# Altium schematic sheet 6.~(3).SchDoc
size 420 x 297 mm
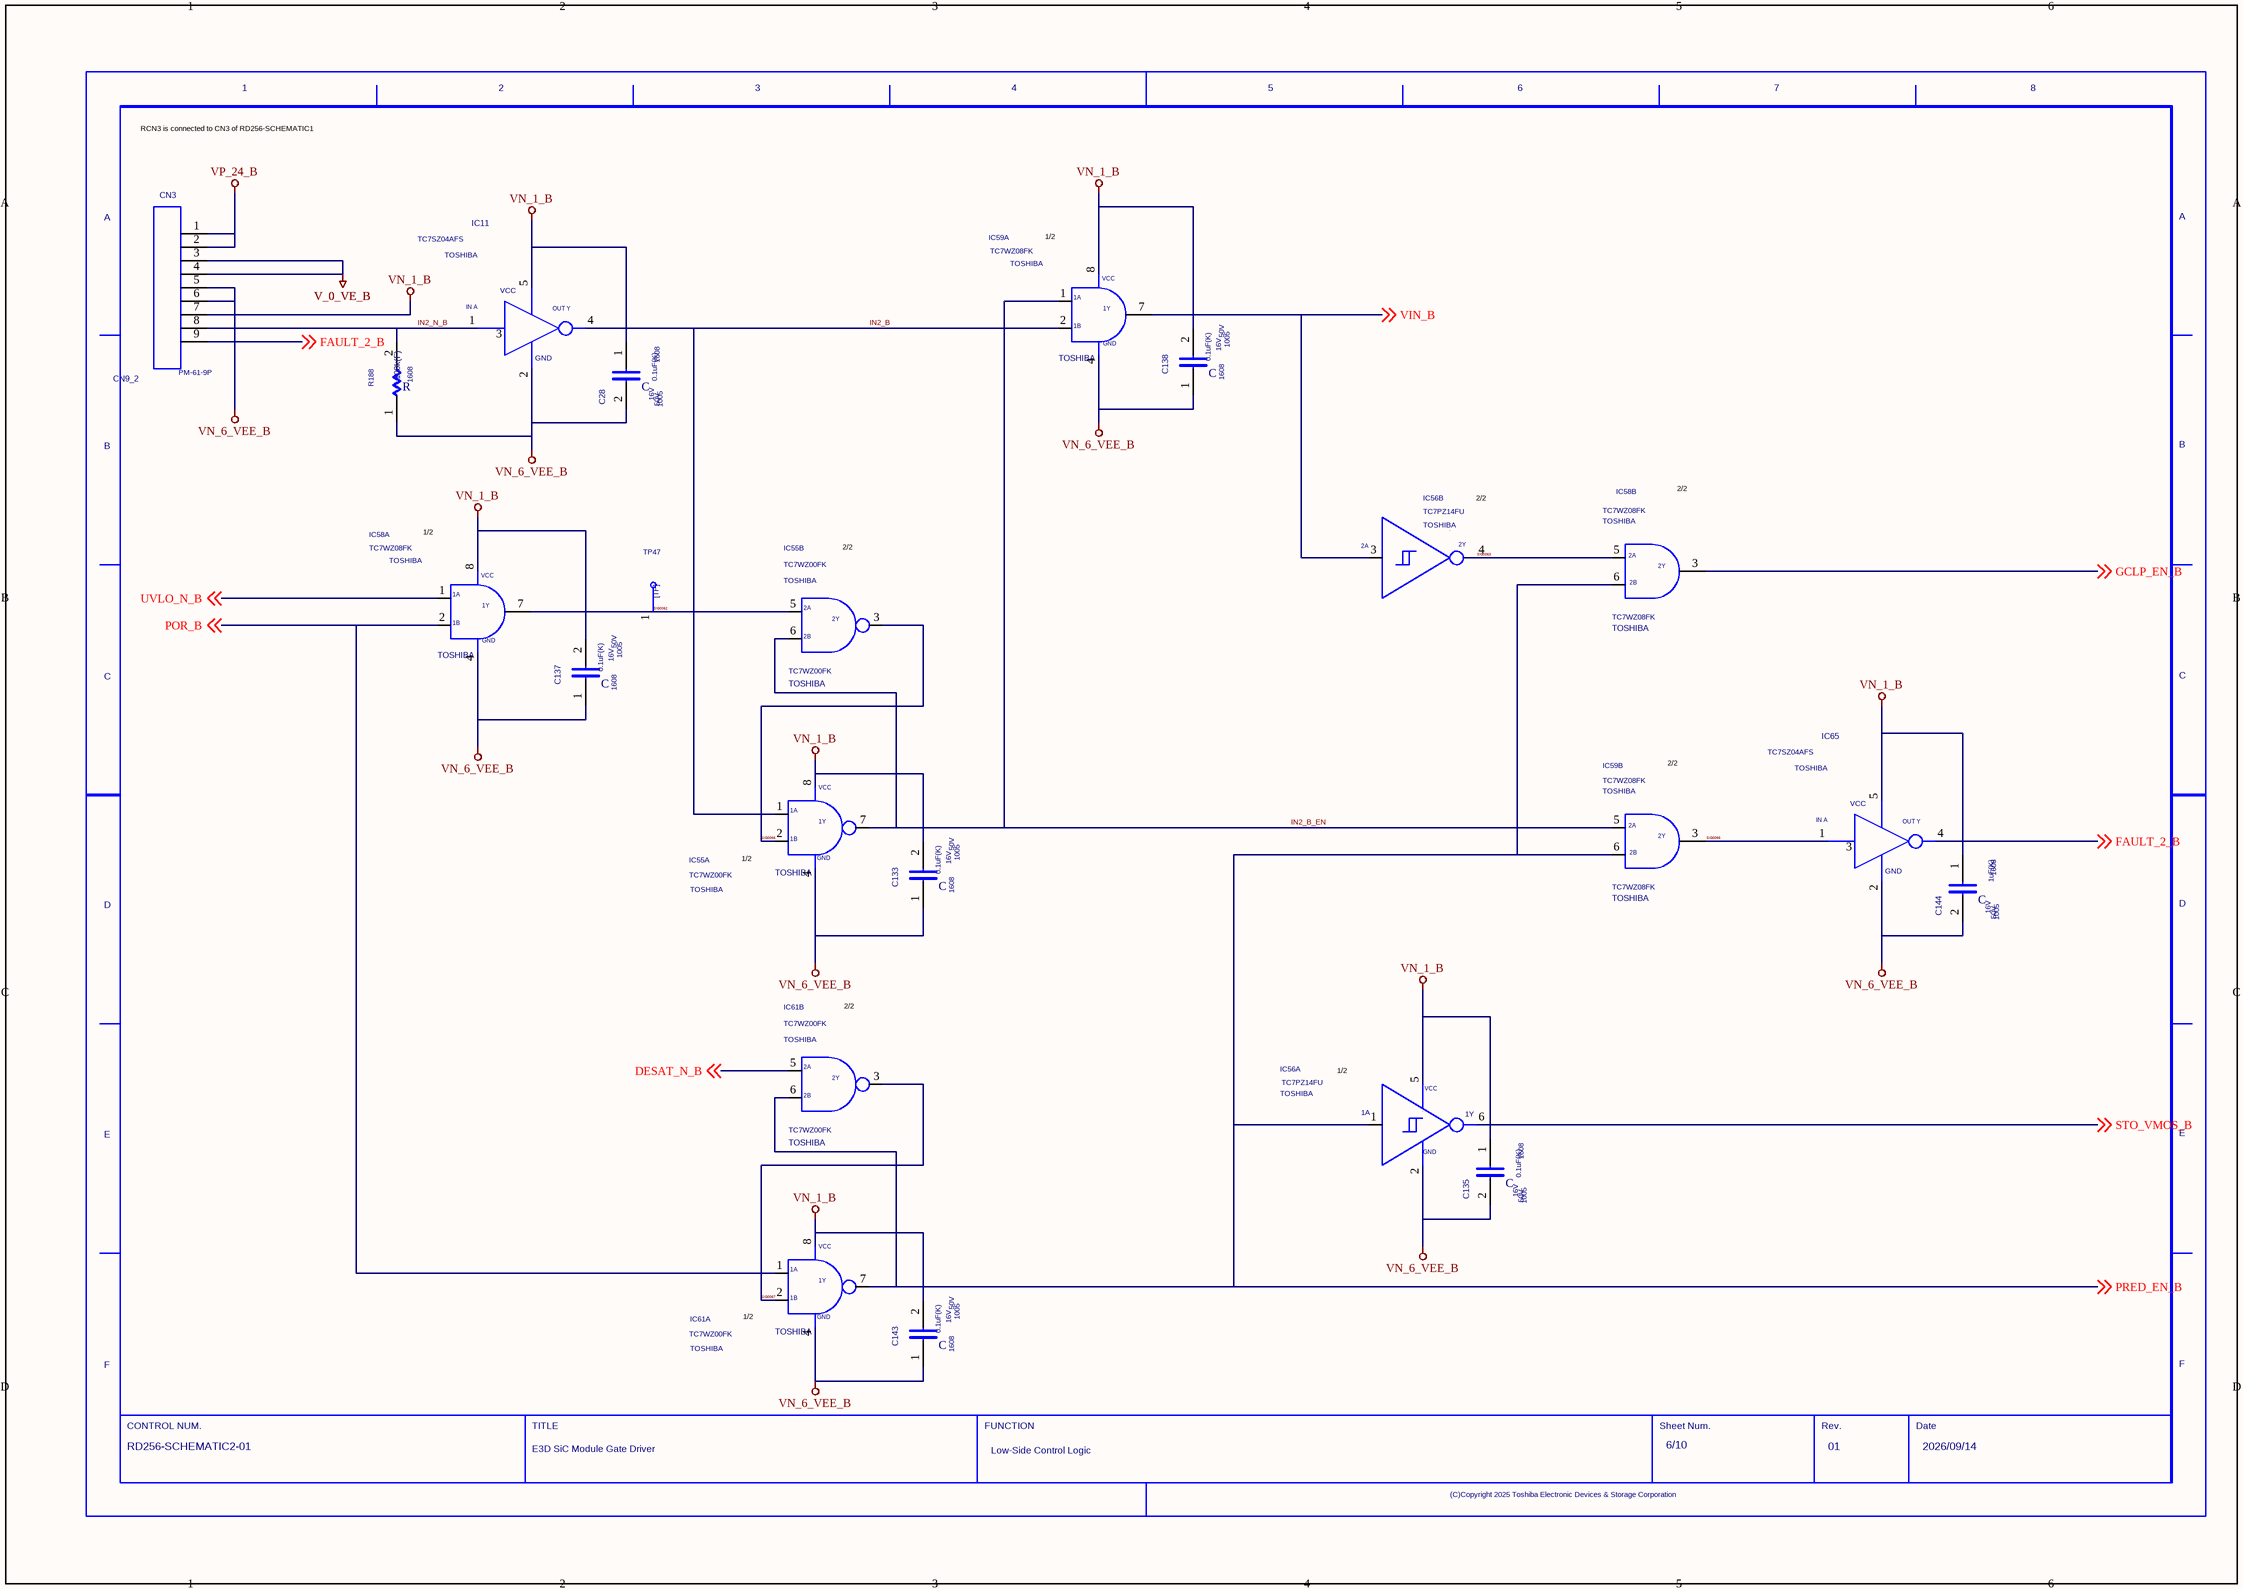
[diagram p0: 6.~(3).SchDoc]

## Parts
C28  VOLTAGE: 16V  CODE: 1005  VAL1: 0.1uF(K)  VAL2: 50V  SIZECODESMD: 1608  (hidden comment: C)
C133  VOLTAGE: 16V  CODE: 1005  VAL1: 0.1uF(K)  VAL2: 50V  SIZECODESMD: 1608  (hidden comment: C)
C135  VOLTAGE: 16V  CODE: 1005  VAL1: 0.1uF(K)  VAL2: 50V  SIZECODESMD: 1608  (hidden comment: C)
C137  VOLTAGE: 16V  CODE: 1005  VAL1: 0.1uF(K)  VAL2: 50V  SIZECODESMD: 1608  (hidden comment: C)
C138  VOLTAGE: 16V  CODE: 1005  VAL1: 0.1uF(K)  VAL2: 50V  SIZECODESMD: 1608  (hidden comment: C)
C143  VOLTAGE: 16V  CODE: 1005  VAL1: 0.1uF(K)  VAL2: 50V  SIZECODESMD: 1608  (hidden comment: C)
C144  VOLTAGE: 16V  CODE: 1005  VAL1: 1uF(K)  VAL2: 50V  SIZECODESMD: 1608  (hidden comment: C)
CN3  CN9_2  VAL3: PM-61-9P
IC11  USERCOMPTEXT3: TOSHIBA  (hidden comment: TC7SZ04AFS)
IC55  VENDOR: TOSHIBA  (hidden comment: TC7WZ00FK)  (parts A,B of 2)
IC56  VAL3: TC7PZ14FU  USERCOMPTEXT3: TOSHIBA  (hidden comment: TC7PZ17FU)  (parts A,B of 2)
IC58  VENDOR: TOSHIBA  (hidden comment: TC7WZ08FK)  (parts A,B of 2)
IC59  VENDOR: TOSHIBA  (hidden comment: TC7WZ08FK)  (parts A,B of 2)
IC61  VENDOR: TOSHIBA  (hidden comment: TC7WZ00FK)  (parts A,B of 2)
IC65  USERCOMPTEXT3: TOSHIBA  (hidden comment: TC7SZ04AFS)
R188  VAL1: 100k(F)  SIZECODESMD: 1608  (hidden comment: R)
TP47  TP  (value not drawn)
U?  REVISION: 01  SHEETNUMBER: 6/10  FUNCTION: Low-Side Control Logic  TITLE: E3D SiC Module Gate Driver  DRAWINGNUMBER: RD256-SCHEMATIC2-01  DATE: 2026/09/14  (hidden comment: WAKU_DEF100)

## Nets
V_0_VE_B: CN3.3 CN3.4
VN_1_B: C28.1 C133.2 C135.1 C137.2 C138.2 C143.2 C144.1 CN3.7 IC11.5 IC55.8 IC56.5 IC58.8 IC59.8 IC61.8 IC65.5
VN_6_VEE_B: C28.2 C133.1 C135.2 C137.1 C138.1 C143.1 C144.2 CN3.5 CN3.6 IC11.2 IC55.4 IC56.2 IC58.4 IC59.4 IC61.4 IC65.2 R188.1
VP_24_B: CN3.1 CN3.2
DESAT_N_B: IC61.5(2A) ; off-sheet DESAT_N_B
FAULT_2_B: CN3.9 IC65.4 ; off-sheet FAULT_2_B
GCLP_EN_B: IC58.3 ; off-sheet GCLP_EN_B
IN2_B: IC11.4 IC55.1 IC59.2
IN2_B_EN: IC55.6(2B) IC55.7 IC59.1 IC59.5
IN2_N_B: CN3.8 IC11.1 R188.2
POR_B: IC58.2 IC61.1 ; off-sheet POR_B
PRED_EN_B: IC56.1 IC58.6 IC59.6 IC61.6(2B) IC61.7 ; off-sheet PRED_EN_B
SIG0062: IC55.5(2A) IC58.7 TP47.1
SIG0063: IC56.4 IC58.5
SIG0065: IC59.3 IC65.1
SIG0066: IC55.2 IC55.3(2Y)
SIG0067: IC61.2 IC61.3(2Y)
STO_VMOS_B: IC56.6 ; off-sheet STO_VMOS_B
UVLO_N_B: IC58.1 ; off-sheet UVLO_N_B
VIN_B: IC56.3 IC59.7 ; off-sheet VIN_B

Not connected (* = marked no-connect by the designer): IC11 3; IC65 3

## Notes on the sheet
- RCN3 is connected to CN3 of RD256-SCHEMATIC1
- (near IC59) 1/2
- (near IC58) 1/2
- 2/2
- (near IC55) 1/2
- (near IC56) 1/2
- (near IC61) 1/2

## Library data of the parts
C28 C133 C135 C137 C138 C143 C144 = C: ORIGINALSYMBOLORIGIN: (0,0); VC2: 0; PSPICETEMPLATE: C^@REFDES %1 %2 ?TOLERANCE¦C^@REFDES¦ @VALUE ?IC/IC=@IC/ TC=@TC1,@TC2 ?TOLERANCE¦\n.model C^@REFDES CAP C=1 DEV=@TOLERANCE% TC1=@TC1 TC2=@TC2 VC1=@VC1 VC2=@VC2¦; SAVECOUNT: 2; UPDATETIME: 08:48:12; UPDATEUSER: HP_Z8_KEYSHOT; INSTANCENAME: INS2265204
CN3 = CN9_1: OriginalSymbolOrigin: (0,0); USER_VALUE: XG4A-1031; PSPICETEMPLATE: X^@REFDES %1 %2 %3 %4 %5 %6 %7 %8 %9 %10 %M1 %M2 @MODEL; SAVECOUNT: 2; UPDATETIME: 08:48:13; UPDATEUSER: HP_Z8_KEYSHOT; INSTANCENAME: INS2253568
IC11 IC65 = TC7SZ04AFS: OriginalSymbolOrigin: (0,-5080); PSPICETEMPLATE: X^@REFDES %INA %GND %NC %OUTY %VCC @MODEL; SAVECOUNT: 6; UPDATETIME: 19:30:29; UPDATEUSER: t5459927; TIME: 11:55:02; INSTANCENAME: INS2254048
IC55 IC61 = TC7WZ00FK_2: PART NUMBER: TC7W00FK; ORIGINALSYMBOLORIGIN: (2540,-2540); DESCRIPTION-A: NAND 2ch Logic; PSPICETEMPLATE: X^@REFDES %1A %1B %2Y %GND %2A %2B %1Y %VCC @MODEL; ・: 7 V; SPLIT_INST: TRUE; ORDER: $pOrder; SWAP_INFO: (S1+S2); SAVECOUNT: 5; UPDATETIME: 16:09:46; UPDATEUSER: sptcae09; TIME: 08:52:39; INSTANCENAME: INS2253652; FUNCN: TC7WZ00FK_1; CaptureCellPackProp: TC7WZ00FK_2A
IC56 = TC7PZ14FU_2: OriginalSymbolOrigin: (5080,15240); SWAP_INFO: (S1+S2); PSPICETEMPLATE: X^@REFDES %1A %GND %2A %2Y %VCC %1Y @MODEL; SPLIT_INST: TRUE; SAVECOUNT: 7; UPDATETIME: 19:09:34; UPDATEUSER: t5459927; TIME: 11:55:01; INSTANCENAME: INS2254016; FUNCN: TC7PZ14FU_1; CaptureCellPackProp: TC7PZ14FU_2A
IC58 IC59 = TC7WZ08FK_1: PART NUMBER: TC7W00FK; ORIGINALSYMBOLORIGIN: (2540,-2540); DESCRIPTION-A: NAND 2ch Logic; PSPICETEMPLATE: X^@REFDES %1A %1B %2Y %GND %2A %2B %1Y %VCC @MODEL; ・: 7 V; SPLIT_INST: TRUE; ORDER: $pOrder; SWAP_INFO: (S1+S2); SAVECOUNT: 5; UPDATETIME: 16:09:46; UPDATEUSER: sptcae09; TIME: 08:52:39; INSTANCENAME: INS2254084; CaptureCellPackProp: TC7WZ08FK_1A
R188 = R: ORIGINALSYMBOLORIGIN: (0,0); PSPICETEMPLATE: R^@REFDES %1 %2 ?TOLERANCE¦R^@REFDES¦ @VALUE TC=@TC1,@TC2 ?TOLERANCE¦\n.model R^@REFDES RES R=1 DEV=@TOLERANCE% TC1=@TC1 TC2=@TC2¦; TC2: 0; VAL2: 100mW; SAVECOUNT: 2; UPDATETIME: 08:48:13; UPDATEUSER: HP_Z8_KEYSHOT; INSTANCENAME: INS2263832
TP47 = TP: ORIGINALSYMBOLORIGIN: (0,0); SAVEAREA0: -242,-92,12810,7836; SAVECOUNT: 2; UPDATETIME: 16:18:11; UPDATEUSER: fukuda-y; TIME: 16:12:21; INSTANCENAME: INS2253720
U? = WAKU_DEF100: OriginalSymbolOrigin: (10160,284480); SAVECOUNT: 4; UPDATETIME: 12:22:00; UPDATEUSER: t5459927; TIME: 14:30:25; SAVEAREA0: -63393,-16950,474261,314592; PLOTTIME: HH:MM; SHTSAVECOUNT: 33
